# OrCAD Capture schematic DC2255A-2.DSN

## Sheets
1 PAGE2: size A; title: 300mA, ULTRA LOW QUIESCENT CURRENT, BUCK-BOOST; rev: 2; company: TM
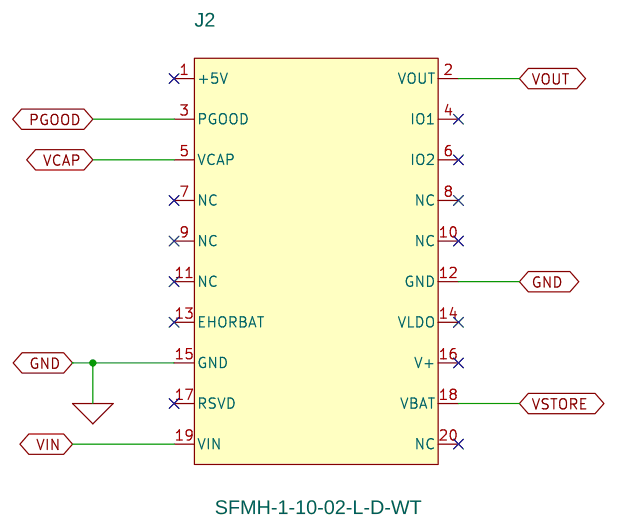
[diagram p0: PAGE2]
2 LTC3106EUDC: size Custom
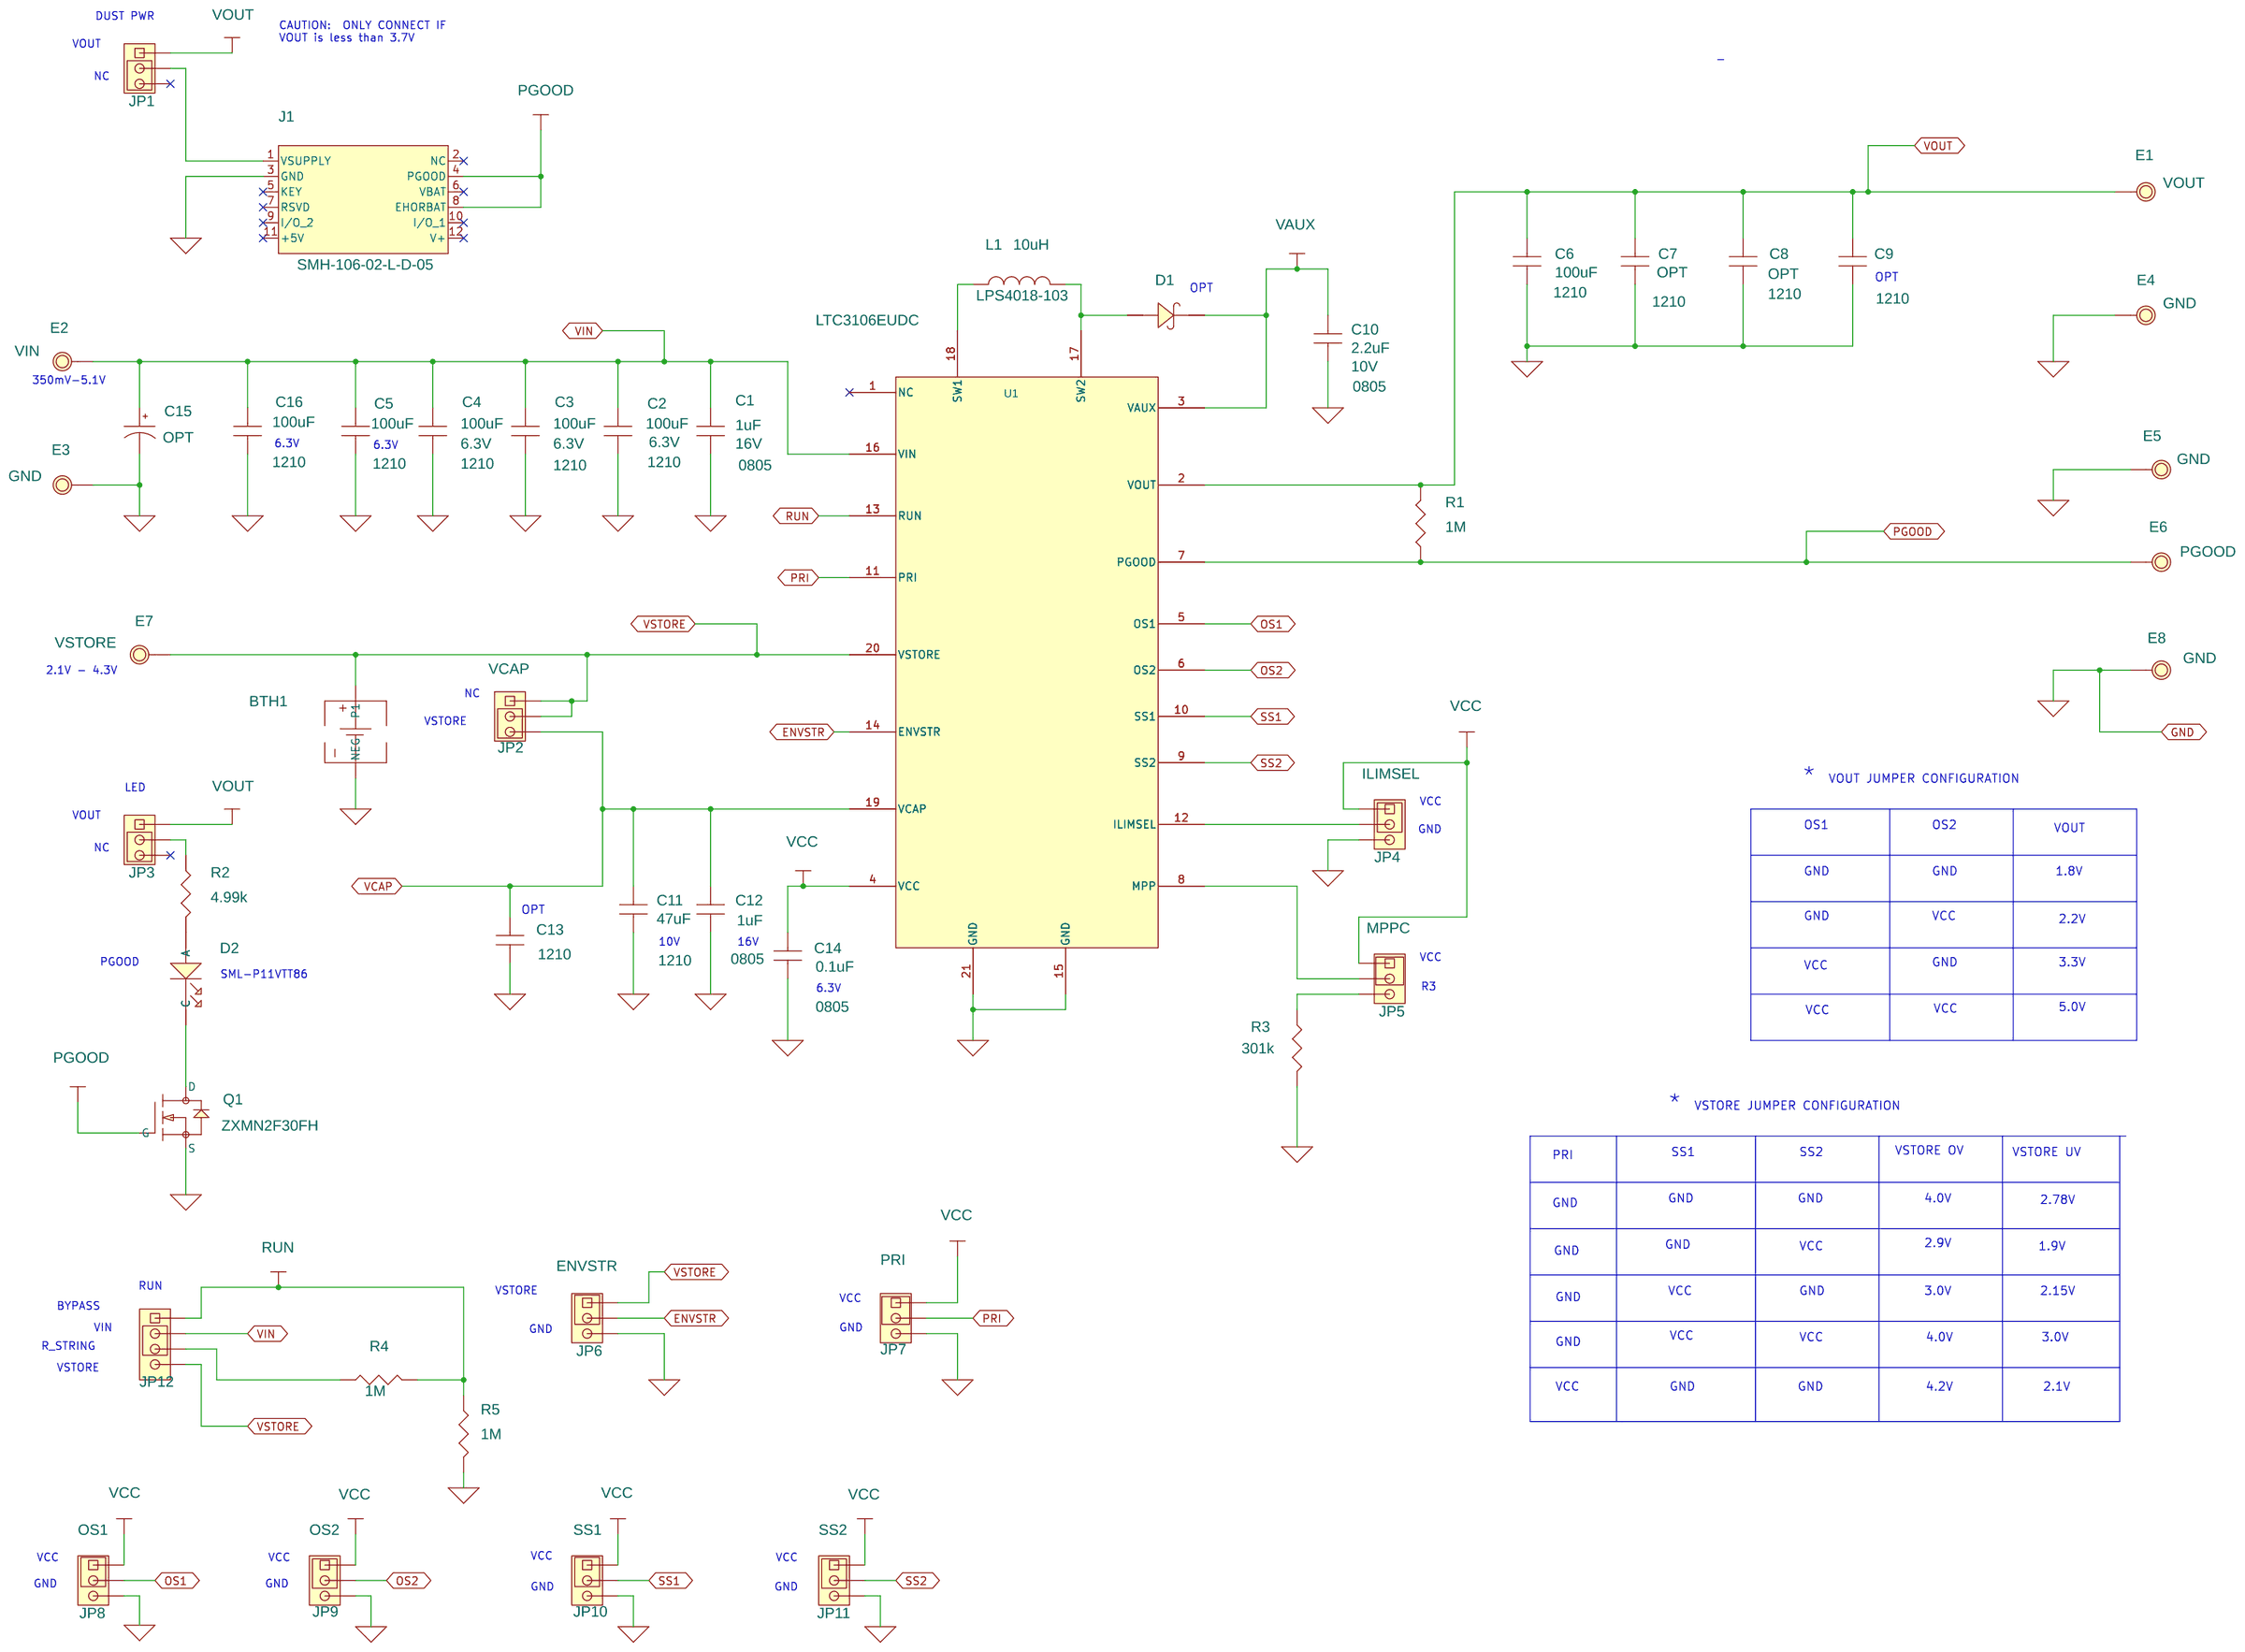
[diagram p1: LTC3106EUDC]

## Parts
sheet LTC3106EUDC
BTH1  SMTU2032-LF  [SMTU2032-LF]
C1  1uF  [0805]
C2  100uF  [1210]
C3  100uF  [1210]
C4  100uF  [1210]
C5  100uF  [1210]
C6  100uF  [1210]
C7  OPT  [1210]
C8  OPT  [1210]
C9  22uF  [1210]
C10  2.2uF  [0805]
C11  47uF  [1210]
C12  1uF  [0805]
C13  22uF  [1210]
C14  0.1uF  [0805]
C15  OPT  [CAP-KR-5R5H104-R]
C16  100uF  [1210]
D1  1A/20V  [SOD323-NXP]
D2  {value}  [LED-SML-P11VTT86]
E1  Testpoint  [PAD150-095]
E2  Testpoint  [PAD150-095]
E3  Testpoint  [PAD150-095]
E4  Testpoint  [PAD150-095]
E5  Testpoint  [PAD150-095]
E6  Testpoint  [PAD150-095]
E7  Testpoint  [PAD150-095]
E8  Testpoint  [PAD150-095]
J1  SMH-106-02-L-D-05  [SMH-12PIN-100-DUST]
JP1  HD1X3-079  [HD1X3-079]
JP2  HD1X3-079  [HD1X3-079]
JP3  HD1X3-079  [HD1X3-079]
JP4  HD1X3-079  [HD1X3-079]
JP5  HD1X3-079  [HD1X3-079]
JP6  HD1X3-079  [HD1X3-079]
JP7  HD1X3-079  [HD1X3-079]
JP8  HD1X3-079  [HD1X3-079]
JP9  HD1X3-079  [HD1X3-079]
JP10  HD1X3-079  [HD1X3-079]
JP11  HD1X3-079  [HD1X3-079]
JP12  HD1X3-079  [HDR\4X1\079]
L1  10uH  [LPS4018]
Q1  ZXMN2F30FH  [ZETEX-SOT23]
R1  1M  [0603]
R2  4.99k  [0603]
R3  301k  [0603]
R4  1M  [0603]
R5  1M  [0603]
U1  LTC3106EUDC  [QFN20EUDC-3X4]
sheet PAGE2
J2  SFMH-1-10-02-L-D-WT  [SFMH-110-02-XXX-D-WT]

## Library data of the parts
BTH1 = HU2032_2
C1 = Capacitor_0805: VOLTAGE RATING: 16V
C2 = Capacitor_1210_4: VOLTAGE RATING: 6.3V
C3 = Capacitor_1210_6: VOLTAGE RATING: 6.3V
C4 = Capacitor_1210_8: VOLTAGE RATING: 6.3V
C5 = Capacitor_1210_7: VOLTAGE RATING: 6.3V
C6 = Capacitor_1210_10: VOLTAGE RATING: 16V
C7 = Capacitor_1210: VOLTAGE RATING: 6.3V
C8 = Capacitor_1210_1: VOLTAGE RATING: 10V
C9 = Capacitor_1210_2: VOLTAGE RATING: 16V
C10 = Capacitor_0805_3: VOLTAGE RATING: 10V
C11 = Capacitor_1210_5
C12 = Capacitor_0805_2
C13 = Capacitor_1210_9: VOLTAGE RATING: 16V
C14 = Capacitor_0805_1
C15 = Capacitor_custom
C16 = Capacitor_1210_3: VOLTAGE RATING: 16V
D1 = PMEG2010EA_0: 6th Part Field: (OPT)
D2 = LED_0402
E1 = MillMax-2501-2: V: VOUT
E2 = MillMax-2501-2: V: VIN
E3-E5 E8 = MillMax-2501-2: V: GND
E6 = MillMax-2501-2: V: PGOOD
E7 = MillMax-2501-2: V: VSTORE
J1 = DUST_HEADER_2X6
JP1 JP3 = HD1X3_12
JP2 = HD1X3_12: silkscreen: VCAP
JP4 = HD1X3_6: silkscreen: ILIMSEL
JP5 = HD1X3_0: silkscreen: MPPC
JP6 = HD1X3_5: silkscreen: ENVSTR
JP7 = HD1X3_0: silkscreen: PRI
JP8 = HD1X3_1: silkscreen: OS1
JP9 = HD1X3_4: silkscreen: OS2
JP10 = HD1X3_2: silkscreen: SS1
JP11 = HD1X3_3: silkscreen: SS2
JP12 = Header_1x4_B_1
L1 = INDUCTOR: PART NUMBER: LPS4018-103
Q1 = ZVN3306_0
R1-R5 = R: V: 1%
U1 = LTC3106_3
J2 = CONN_10x2_10

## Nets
GND: BTH1.2(NEG) C1.2 C2.2 C3.2 C4.2 C5.2 C6.2 C7.2 C8.2 C9.2 C10.2 C11.2 C12.2 C13.2 C14.2 C15.- C16.2 E3.1 E4.1 E5.1 E8.1 J1.3(GND) J2.12(GND) J2.15(GND) JP4.3 JP6.3 JP7.3 JP8.3 JP9.3 JP10.3 JP11.3 Q1.2(S) R3.2 R5.2 U1.15(GND) U1.21(GND)
VCC: C14.1 JP4.1 JP5.1 JP7.1 JP8.1 JP9.1 JP10.1 JP11.1 U1.4(VCC)
VIN: C1.1 C2.1 C3.1 C4.1 C5.1 C15.+ C16.1 E2.1 J2.19(VIN) JP12.2 U1.16(VIN)
ENVSTR: JP6.2 U1.14(ENVSTR)
OS1: JP8.2 U1.5(OS1)
OS2: JP9.2 U1.6(OS2)
PGOOD: E6.1 J1.4(PGOOD) J1.8(EHORBAT) J2.3(PGOOD) Q1.1(G) R1.1 U1.7(PGOOD)
PRI: JP7.2 U1.11(PRI)
RUN: JP12.1 R4.2 R5.1 U1.13(RUN)
SS1: JP10.2 U1.10(SS1)
SS2: JP11.2 U1.9(SS2)
VAUX: C10.1 D1.1(K) U1.3(VAUX)
VCAP: C11.1 C12.1 C13.1 J2.5(VCAP) JP2.3 U1.19(VCAP)
VOUT: C6.1 C7.1 C8.1 C9.1 E1.1 J2.2(VOUT) JP1.1 JP3.1 R1.2 U1.2(VOUT)
VSTORE: BTH1.1(P1) E7.1 J2.18(VBAT) JP2.1 JP2.2 JP6.1 JP12.4 U1.20(VSTORE)
N16593241: J1.1(VSUPPLY) JP1.2
N16654703: JP3.2 R2.1
N16761736: D2.2(C) Q1.3(D)
N16769001: L1.1 U1.18(SW1)
N16769110: D1.2(A) L1.2 U1.17(SW2)
N16809802: JP12.3 R4.1
N16818999: JP5.2 U1.8(MPP)
N16819368: JP4.2 U1.12(ILIMSEL)
N16820126: JP5.3 R3.1
N17195237: D2.1(A) R2.2

Not connected (* = marked no-connect by the designer): J1 2(NC)* 5(KEY)* 6(VBAT)* 7(RSVD)* 9(I/O_2)* 10(I/O_1)* 11(+5V)* 12(V+)*; J2 1(+5V)* 4(IO1)* 6(IO2)* 7(NC)* 8(NC)* 9(NC)* 10(NC)* 11(NC)* 13(EHORBAT)* 14(VLDO)* 16(V+)* 17(RSVD)* 20(NC)*; JP1 3*; JP3 3*; U1 1(NC)*

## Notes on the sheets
sheet 2
- DUST PWR
- CAUTION:  ONLY CONNECT IF
  VOUT is less than 3.7V
- VOUT
- -
- NC
- OPT
- OPT
- 350mV-5.1V
- 6.3V
- 6.3V
- 2.1V - 4.3V
- NC
- VSTORE
- *
- VOUT JUMPER CONFIGURATION
- LED
- VOUT
- VCC
- GND
- OS1
- OS2
- VOUT
- NC
- GND
- GND
- 1.8V
- OPT
- GND
- VCC
- 2.2V
- 10V
- 16V
- PGOOD
- VCC
- VCC
- GND
- 3.3V
- SML-P11VTT86
- 6.3V
- R3
- VCC
- VCC
- 5.0V
- *
- VSTORE JUMPER CONFIGURATION
- PRI
- SS1
- SS2
- VSTORE OV
- VSTORE UV
- GND
- GND
- 4.0V
- 2.78V
- GND
- GND
- GND
- VCC
- 2.9V
- 1.9V
- RUN
- VSTORE
- VCC
- GND
- 3.0V
- 2.15V
- BYPASS
- VCC
- GND
- VIN
- GND
- GND
- R_STRING
- GND
- VCC
- VCC
- 4.0V
- 3.0V
- VSTORE
- VCC
- GND
- GND
- 4.2V
- 2.1V
- VCC
- VCC
- VCC
- VCC
- GND
- GND
- GND
- GND
